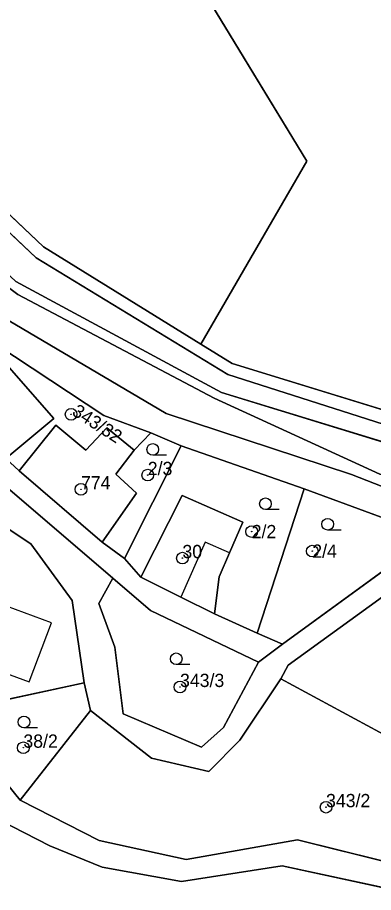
# Model space of a CAD drawing. Extents: x -652854 to -650068, y -1097661 to -1095417.
# Drawn here: x -650617.2 to -650571.5, y -1096161.2 to -1096048.9 of the extents above; entities that cross this region are included whole.
import ezdxf

# ---------------------------------------------------------------- set-up
doc = ezdxf.new("R2010")
doc.units = 0
for name, color, linetype in [('Definiční body parcel', 7, 'Continuous'), ('Hranice - vnitř_ kresba', 7, 'Continuous'), ('Hranice parcel', 7, 'Continuous'), ('Obvody jako plochy', 7, 'Continuous'), ('Parcelní čísla', 7, 'Continuous'), ('Značky kultur', 7, 'Continuous')]:
    doc.layers.add(name, color=color, linetype=linetype)

msp = doc.modelspace()

# ---------------------------------------------------------------- linework, layer by layer
at = {"layer": 'Definiční body parcel'}
for centre, radius in [((-650610.34, -1096099.79), 0.75), ((-650610.34, -1096099.79), 0.0327), ((-650600.49, -1096107.59), 0.75), ((-650600.49, -1096107.59), 0.0327), ((-650609.07, -1096109.42), 0.75), ((-650609.07, -1096109.42), 0.0327), ((-650587.14, -1096114.84), 0.75), ((-650587.14, -1096114.84), 0.0327), ((-650579.36, -1096117.35), 0.75), ((-650596.04, -1096118.25), 0.75), ((-650596.04, -1096118.25), 0.0327), ((-650579.36, -1096117.35), 0.0327), ((-650596.35, -1096134.79), 0.75), ((-650596.35, -1096134.79), 0.0327), ((-650616.47, -1096142.58), 0.75), ((-650616.47, -1096142.58), 0.0327), ((-650577.59, -1096150.21), 0.75), ((-650577.59, -1096150.21), 0.0327)]:
    msp.add_circle(centre, radius, dxfattribs=at)
at = {"layer": 'Hranice - vnitř_ kresba'}
for p, q in [((-650593.12, -1096116.2), (-650596.25, -1096123.25)), ((-650590.01, -1096117.56), (-650593.12, -1096116.2)), ((-650612.87, -1096126.56), (-650624.73, -1096122.18)), ((-650615.72, -1096134.13), (-650612.87, -1096126.56)), ((-650627.53, -1096129.77), (-650615.72, -1096134.13))]:
    msp.add_line(p, q, dxfattribs=at)
at = {"layer": 'Hranice parcel'}
for p, q in [((-650580.06, -1096067.29), (-650611.4, -1096015.81)), ((-650613.9, -1096078.29), (-650644.26, -1096049.61)), ((-650644.87, -1096051.4), (-650614.84, -1096079.7)), ((-650617.17, -1096084.43), (-650650.59, -1096059.53)), ((-650593.69, -1096090.8), (-650580.06, -1096067.29)), ((-650593.69, -1096090.8), (-650613.9, -1096078.29)), ((-650614.84, -1096079.7), (-650590.19, -1096094.69)), ((-650591.02, -1096096.97), (-650617.43, -1096082.74)), ((-650591.97, -1096097.7), (-650617.17, -1096084.43)), ((-650619.23, -1096087.24), (-650598.12, -1096099.67)), ((-650612.56, -1096100.32), (-650622.17, -1096089.39)), ((-650606.12, -1096099.96), (-650622.17, -1096089.39)), ((-650589.64, -1096093.25), (-650593.69, -1096090.8)), ((-650567.4, -1096100.11), (-650589.64, -1096093.25)), ((-650590.19, -1096094.69), (-650569.19, -1096101.41)), ((-650552.14, -1096108.91), (-650591.02, -1096096.97)), ((-650570.66, -1096107.46), (-650591.97, -1096097.7)), ((-650618.72, -1096105.47), (-650612.56, -1096100.32)), ((-650600.08, -1096102.18), (-650606.12, -1096099.96)), ((-650598.12, -1096099.67), (-650574.33, -1096107.51)), ((-650612.29, -1096101.19), (-650617.01, -1096107.04)), ((-650608.43, -1096104.38), (-650612.29, -1096101.19)), ((-650605.76, -1096101.52), (-650608.43, -1096104.38)), ((-650602.22, -1096104.41), (-650605.76, -1096101.52)), ((-650600.08, -1096102.18), (-650602.22, -1096104.41)), ((-650596.19, -1096103.84), (-650600.08, -1096102.18)), ((-650602.22, -1096104.41), (-650604.6, -1096107.46)), ((-650596.19, -1096103.84), (-650603.46, -1096118.31)), ((-650580.42, -1096109.36), (-650596.19, -1096103.84)), ((-650618.72, -1096105.47), (-650617.01, -1096107.04)), ((-650617.01, -1096107.04), (-650606.36, -1096116.18)), ((-650604.6, -1096107.46), (-650601.93, -1096109.9)), ((-650574.33, -1096107.51), (-650543.65, -1096119.5)), ((-650586.43, -1096127.86), (-650580.42, -1096109.36)), ((-650563.99, -1096115.37), (-650580.42, -1096109.36)), ((-650604.96, -1096120.83), (-650618.19, -1096109.5)), ((-650601.93, -1096109.9), (-650606.36, -1096116.18)), ((-650601.39, -1096120.7), (-650596.06, -1096110.2)), ((-650596.06, -1096110.2), (-650588.27, -1096113.62)), ((-650615.51, -1096116.41), (-650621.16, -1096112.71)), ((-650588.27, -1096113.62), (-650590.01, -1096117.56)), ((-650610.21, -1096123.67), (-650615.51, -1096116.41)), ((-650606.36, -1096116.18), (-650603.46, -1096118.31)), ((-650603.46, -1096118.31), (-650601.39, -1096120.7)), ((-650590.01, -1096117.56), (-650591.3, -1096120.66)), ((-650583.19, -1096129.29), (-650568.37, -1096118.51)), ((-650606.79, -1096124.05), (-650604.96, -1096120.83)), ((-650604.96, -1096120.83), (-650600.15, -1096124.96)), ((-650596.25, -1096123.25), (-650601.39, -1096120.7)), ((-650591.3, -1096120.66), (-650591.93, -1096125.39)), ((-650567.85, -1096121.43), (-650582.46, -1096131.98)), ((-650608.67, -1096134.27), (-650610.21, -1096123.67)), ((-650591.93, -1096125.39), (-650596.25, -1096123.25)), ((-650604.72, -1096129.69), (-650606.79, -1096124.05)), ((-650600.15, -1096124.96), (-650586.28, -1096131.6)), ((-650591.93, -1096125.39), (-650586.43, -1096127.86)), ((-650586.43, -1096127.86), (-650583.19, -1096129.29)), ((-650583.19, -1096129.29), (-650586.28, -1096131.6)), ((-650603.65, -1096138.24), (-650604.72, -1096129.69)), ((-650586.28, -1096131.6), (-650590.77, -1096139.99)), ((-650582.46, -1096131.98), (-650583.41, -1096133.73)), ((-650583.41, -1096133.73), (-650588.66, -1096141.6)), ((-650583.41, -1096133.73), (-650567.54, -1096142.3)), ((-650608.67, -1096134.27), (-650621.14, -1096136.95)), ((-650607.86, -1096137.79), (-650608.67, -1096134.27)), ((-650607.86, -1096137.79), (-650616.9, -1096149.29)), ((-650600.02, -1096143.9), (-650607.86, -1096137.79)), ((-650593.59, -1096142.5), (-650603.65, -1096138.24)), ((-650590.77, -1096139.99), (-650593.59, -1096142.5)), ((-650588.66, -1096141.6), (-650592.63, -1096145.65)), ((-650621.79, -1096143.29), (-650616.9, -1096149.29)), ((-650592.63, -1096145.65), (-650600.02, -1096143.9)), ((-650616.9, -1096149.29), (-650606.75, -1096154.47)), ((-650613.07, -1096155.16), (-650619.62, -1096151.84)), ((-650606.36, -1096157.89), (-650613.07, -1096155.16)), ((-650606.75, -1096154.47), (-650595.54, -1096156.94)), ((-650595.54, -1096156.94), (-650581.24, -1096154.39)), ((-650581.24, -1096154.39), (-650560.2, -1096159.64)), ((-650596.15, -1096159.76), (-650606.36, -1096157.89)), ((-650583.23, -1096157.75), (-650596.15, -1096159.76)), ((-650562.08, -1096162.3), (-650583.23, -1096157.75))]:
    msp.add_line(p, q, dxfattribs=at)
at = {"layer": 'Obvody jako plochy'}
for points in [[(-650613.9, -1096078.29), (-650593.69, -1096090.8), (-650580.06, -1096067.29), (-650611.4, -1096015.81), (-650627.52, -1095958.3), (-650626.69, -1095945), (-650650.16, -1095955.09), (-650655.71, -1095966.27), (-650655.69, -1095990.58), (-650663.2, -1096025.43), (-650644.26, -1096049.61)], [(-650466.48, -1095968.02), (-650476.14, -1095976.88), (-650487.55, -1095984.67), (-650493.33, -1095977.79), (-650503.12, -1095978.41), (-650517.67, -1095964.75), (-650536.05, -1095967.37), (-650541.4, -1095948.01), (-650560.74, -1095953.56), (-650598.64, -1095956.71), (-650612.04, -1095953.51), (-650627.52, -1095958.3), (-650611.4, -1096015.81), (-650580.06, -1096067.29), (-650593.69, -1096090.8), (-650589.64, -1096093.25), (-650567.4, -1096100.11), (-650500.85, -1096112.74), (-650484.72, -1096066.48), (-650468.1, -1096026.43), (-650458, -1096008.78), (-650450.36, -1095987.68), (-650448.82, -1095982.83)], [(-650677.76, -1096007.67), (-650674.5, -1096019.48), (-650644.87, -1096051.4), (-650614.84, -1096079.7), (-650590.19, -1096094.69), (-650569.19, -1096101.41), (-650502.24, -1096119.18), (-650500.85, -1096112.74), (-650567.4, -1096100.11), (-650589.64, -1096093.25), (-650593.69, -1096090.8), (-650613.9, -1096078.29), (-650644.26, -1096049.61), (-650663.2, -1096025.43), (-650675.32, -1096003.13)], [(-650503.38, -1096122.58), (-650530.36, -1096115.03), (-650552.14, -1096108.91), (-650591.02, -1096096.97), (-650617.43, -1096082.74), (-650647, -1096055.18), (-650650.59, -1096059.53), (-650617.17, -1096084.43), (-650591.97, -1096097.7), (-650570.66, -1096107.46), (-650548.77, -1096111.5), (-650518.22, -1096125.08), (-650504.25, -1096126.33)], [(-650485.01, -1096136.73), (-650504.25, -1096126.33), (-650518.22, -1096125.08), (-650548.77, -1096111.5), (-650570.66, -1096107.46), (-650591.97, -1096097.7), (-650617.17, -1096084.43), (-650650.59, -1096059.53), (-650652.3, -1096061.47), (-650619.23, -1096087.24), (-650598.12, -1096099.67), (-650574.33, -1096107.51), (-650543.65, -1096119.5), (-650487.47, -1096142.31)], [(-650622.17, -1096089.39), (-650628.06, -1096093.92), (-650618.72, -1096105.47), (-650612.56, -1096100.32)], [(-650600.08, -1096102.18), (-650606.12, -1096099.96), (-650622.17, -1096089.39), (-650612.56, -1096100.32), (-650618.72, -1096105.47), (-650617.01, -1096107.04), (-650612.29, -1096101.19), (-650608.43, -1096104.38), (-650605.76, -1096101.52), (-650602.22, -1096104.41)], [(-650617.01, -1096107.04), (-650606.36, -1096116.18), (-650601.93, -1096109.9), (-650604.6, -1096107.46), (-650602.22, -1096104.41), (-650605.76, -1096101.52), (-650608.43, -1096104.38), (-650612.29, -1096101.19)], [(-650600.08, -1096102.18), (-650602.22, -1096104.41), (-650604.6, -1096107.46), (-650601.93, -1096109.9), (-650606.36, -1096116.18), (-650603.46, -1096118.31), (-650596.19, -1096103.84)], [(-650603.46, -1096118.31), (-650601.39, -1096120.7), (-650596.06, -1096110.2), (-650588.27, -1096113.62), (-650590.01, -1096117.56), (-650591.3, -1096120.66), (-650591.93, -1096125.39), (-650586.43, -1096127.86), (-650580.42, -1096109.36), (-650596.19, -1096103.84)], [(-650563.99, -1096115.37), (-650580.42, -1096109.36), (-650586.43, -1096127.86), (-650583.19, -1096129.29), (-650568.37, -1096118.51)], [(-650601.39, -1096120.7), (-650596.25, -1096123.25), (-650591.93, -1096125.39), (-650591.3, -1096120.66), (-650590.01, -1096117.56), (-650588.27, -1096113.62), (-650596.06, -1096110.2)], [(-650615.51, -1096116.41), (-650621.16, -1096112.71), (-650626.47, -1096114.06), (-650631.48, -1096126.61), (-650636.49, -1096126.21), (-650629.89, -1096136.31), (-650621.79, -1096143.29), (-650621.14, -1096136.95), (-650608.67, -1096134.27), (-650610.21, -1096123.67)], [(-650586.28, -1096131.6), (-650600.15, -1096124.96), (-650604.96, -1096120.83), (-650606.79, -1096124.05), (-650604.72, -1096129.69), (-650603.65, -1096138.24), (-650593.59, -1096142.5), (-650590.77, -1096139.99)], [(-650582.46, -1096131.98), (-650583.41, -1096133.73), (-650567.54, -1096142.3), (-650565.37, -1096144.05), (-650563.71, -1096141.85), (-650565.49, -1096140.5), (-650564.51, -1096139.21), (-650565.09, -1096138.78), (-650562.09, -1096134.8), (-650559.75, -1096136.57), (-650559.68, -1096136.49), (-650553.85, -1096140.89), (-650549.23, -1096132.62), (-650557.2, -1096124.66), (-650567.85, -1096121.43)], [(-650583.41, -1096133.73), (-650588.66, -1096141.6), (-650592.63, -1096145.65), (-650600.02, -1096143.9), (-650607.86, -1096137.79), (-650616.9, -1096149.29), (-650606.75, -1096154.47), (-650595.54, -1096156.94), (-650581.24, -1096154.39), (-650560.2, -1096159.64), (-650525.22, -1096173.84), (-650524.77, -1096172.87), (-650548.23, -1096158.84), (-650565.37, -1096144.05), (-650567.54, -1096142.3)], [(-650621.79, -1096143.29), (-650616.9, -1096149.29), (-650607.86, -1096137.79), (-650608.67, -1096134.27), (-650621.14, -1096136.95)]]:
    msp.add_lwpolyline(points, close=True, dxfattribs=at)
for points in [[(-650487.47, -1096142.31), (-650543.65, -1096119.5), (-650574.33, -1096107.51), (-650598.12, -1096099.67), (-650619.23, -1096087.24), (-650652.3, -1096061.47), (-650672.13, -1096042.67), (-650677.28, -1096037.27), (-650694.38, -1096015.72), (-650704.37, -1096006.4), (-650697.15, -1096019.65), (-650676, -1096045.2), (-650657.72, -1096061.89), (-650654.45, -1096064.83), (-650638.31, -1096077.32), (-650622.17, -1096089.39), (-650606.12, -1096099.96), (-650600.08, -1096102.18), (-650596.19, -1096103.84), (-650580.42, -1096109.36), (-650563.99, -1096115.37), (-650540.89, -1096125.03), (-650477, -1096151.73)], [(-650502.24, -1096119.18), (-650569.19, -1096101.41), (-650590.19, -1096094.69), (-650614.84, -1096079.7), (-650644.87, -1096051.4), (-650674.5, -1096019.48), (-650677.76, -1096007.67), (-650678.52, -1096007.34), (-650680.34, -1096011.35), (-650676.77, -1096020.11), (-650663.49, -1096034.8), (-650651.25, -1096050.31), (-650647, -1096055.18), (-650617.43, -1096082.74), (-650591.02, -1096096.97), (-650552.14, -1096108.91), (-650530.36, -1096115.03), (-650503.38, -1096122.58), (-650433.69, -1096137.29)], [(-650618.19, -1096109.5), (-650604.96, -1096120.83), (-650600.15, -1096124.96), (-650586.28, -1096131.6), (-650583.19, -1096129.29), (-650586.43, -1096127.86), (-650591.93, -1096125.39), (-650596.25, -1096123.25), (-650601.39, -1096120.7), (-650603.46, -1096118.31), (-650606.36, -1096116.18), (-650617.01, -1096107.04), (-650618.72, -1096105.47)], [(-650568.37, -1096118.51), (-650583.19, -1096129.29), (-650586.28, -1096131.6), (-650590.77, -1096139.99), (-650593.59, -1096142.5), (-650603.65, -1096138.24), (-650604.72, -1096129.69), (-650606.79, -1096124.05), (-650604.96, -1096120.83), (-650618.19, -1096109.5)], [(-650621.16, -1096112.71), (-650615.51, -1096116.41), (-650610.21, -1096123.67), (-650608.67, -1096134.27), (-650607.86, -1096137.79), (-650600.02, -1096143.9), (-650592.63, -1096145.65), (-650588.66, -1096141.6), (-650583.41, -1096133.73), (-650582.46, -1096131.98), (-650567.85, -1096121.43)], [(-650525.22, -1096173.84), (-650560.2, -1096159.64), (-650581.24, -1096154.39), (-650595.54, -1096156.94), (-650606.75, -1096154.47), (-650616.9, -1096149.29), (-650621.79, -1096143.29), (-650629.89, -1096136.31), (-650636.49, -1096126.21), (-650640.31, -1096116.49), (-650643.15, -1096117.33), (-650637.83, -1096129.97), (-650631.31, -1096139.99), (-650624.55, -1096145.32), (-650619.62, -1096151.84), (-650613.07, -1096155.16), (-650606.36, -1096157.89), (-650596.15, -1096159.76), (-650583.23, -1096157.75), (-650562.08, -1096162.3)], [(-650562.08, -1096162.3), (-650583.23, -1096157.75), (-650596.15, -1096159.76), (-650606.36, -1096157.89), (-650613.07, -1096155.16), (-650619.62, -1096151.84)]]:
    msp.add_lwpolyline(points, dxfattribs=at)
at = {"layer": 'Značky kultur'}
for p, q in [((-650598.1, -1096105.05), (-650599.85, -1096105.05)), ((-650583.62, -1096112.02), (-650585.37, -1096112.02)), ((-650575.63, -1096114.65), (-650577.38, -1096114.65)), ((-650595.08, -1096131.92), (-650596.83, -1096131.92)), ((-650614.64, -1096140.03), (-650616.39, -1096140.03))]:
    msp.add_line(p, q, dxfattribs=at)
for centre in [(-650599.85, -1096104.3), (-650585.37, -1096111.27), (-650577.38, -1096113.9), (-650596.83, -1096131.17), (-650616.39, -1096139.28)]:
    msp.add_circle(centre, 0.75, dxfattribs=at)

# ---------------------------------------------------------------- texts
at = {"layer": 'Parcelní čísla'}
msp.add_text('343/32', height=1.7, rotation=326.961, dxfattribs=at).set_placement((-650610.34, -1096099.79))
for s, p in [('2/3', (-650600.49, -1096107.59)), ('774', (-650609.07, -1096109.42)), ('2/2', (-650587.14, -1096115.69)), ('30', (-650596.04, -1096118.25)), ('2/4', (-650579.36, -1096118.2)), ('343/3', (-650596.35, -1096134.79)), ('38/2', (-650616.47, -1096142.58)), ('343/2', (-650577.59, -1096150.21))]:
    msp.add_text(s, height=1.7, dxfattribs=at).set_placement(p)

doc.saveas('drawing.dxf')
